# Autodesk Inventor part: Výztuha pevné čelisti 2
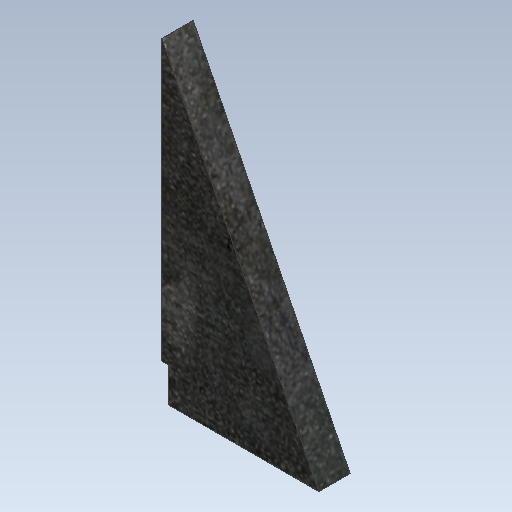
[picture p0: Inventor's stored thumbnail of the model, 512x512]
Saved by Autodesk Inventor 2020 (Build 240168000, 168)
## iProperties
Created: 2025-03
Part Number: Výztuha pevné čelisti 2
Material: Ocel
Document SubType Name: Modeling
Designer: doma
Density: 7.85 g/cm^3
Appearance: Plech
Mass: 194.523 g
Surface Area: 75.7403 cm^2
Volume: 24.78 cm^3
Author: doma
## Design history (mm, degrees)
sketch "Náčrt1"
  geometry: L1 (0, 0)-(50, 0); L2 (0, 0)-(0, 100); L3 (0, 100)-(50, 0)
  constraints: 6 end point, 1 horizontal, 1 vertical
  dimensions: "d0" = 50 distance of L1.start L1.end; "d1" = 100 distance of L1.start L2.end
extrude "Vysunutí1" new body sketch "Náčrt1" distance "d2" = 10; taper "d3" = 0 deg
sketch "Náčrt2"
  geometry: L1 (0, 0)-(-50, 0) reference; L2 (-2, 0)-(-2, 11); L3 (-2, 11)-(0, 11); L4 (0, 100)-(0, 0) reference
  constraints: 4 end point, 2 point on line, 1 perpendicular, 1 vertical
  dimensions: "d4" = 11 distance of L2.start L2.end; "d5" = 2 distance of L2.end L3.end
extrude "Vysunutí2" cut sketch "Náčrt2" distance "d6" = 10; taper "d7" = 0 deg
node "Těleso1"
